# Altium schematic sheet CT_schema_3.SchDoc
size 294 x 169 mm
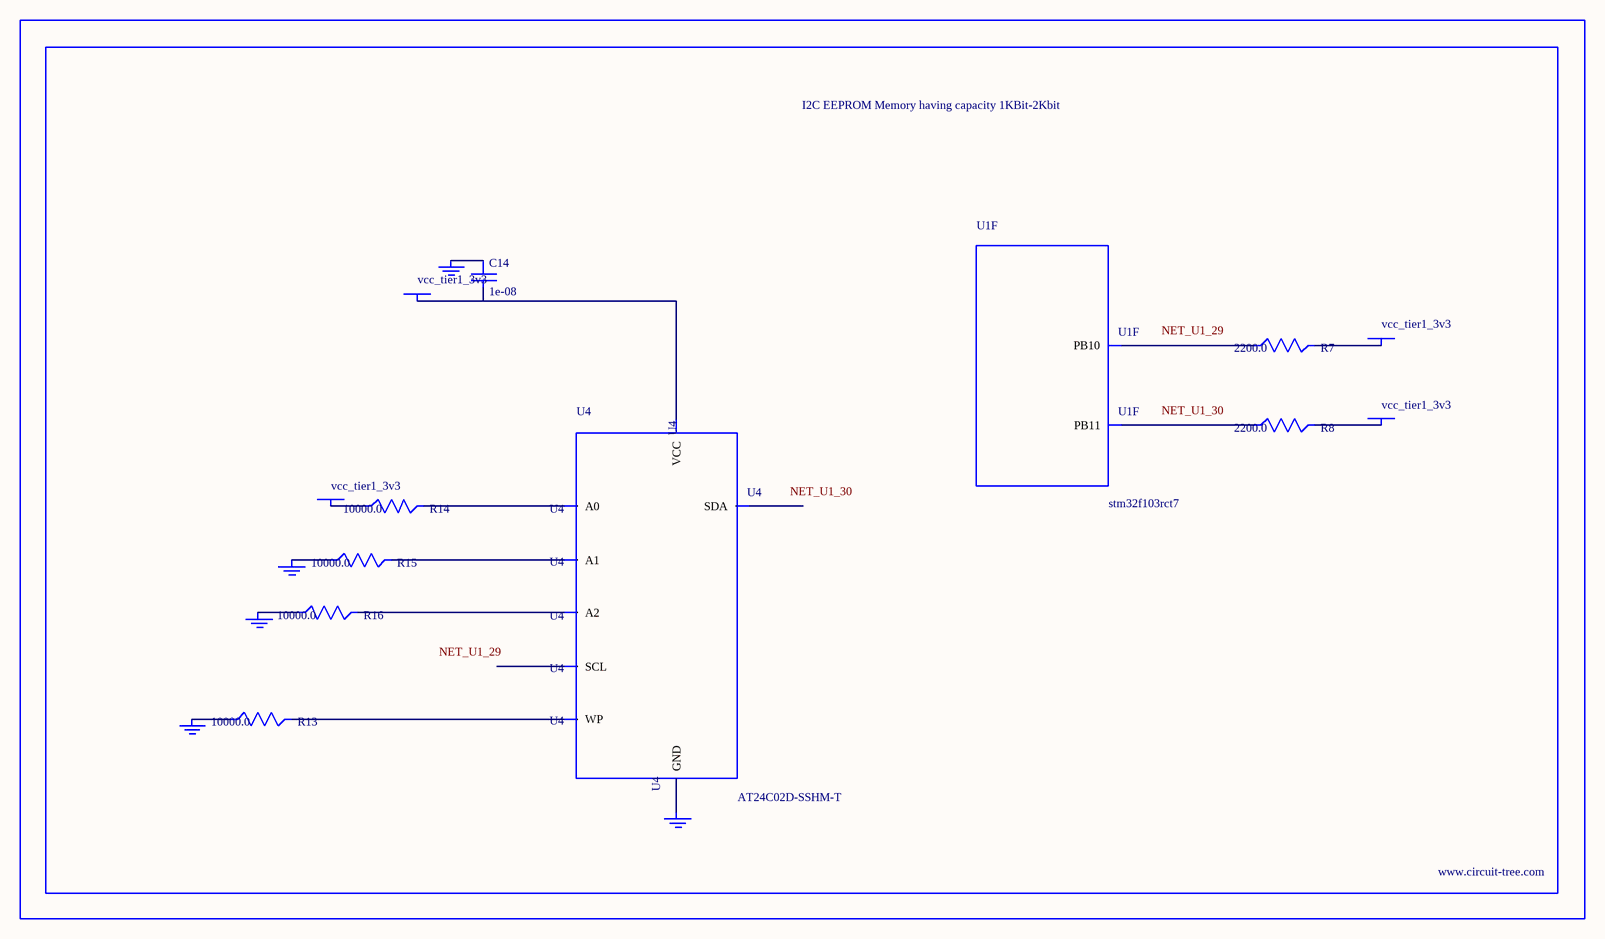
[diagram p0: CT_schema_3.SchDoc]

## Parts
BORDER2  (no value)
C14  1e-08  [C0402]
GND_INSTANCE_2_0  (no value)
GND_INSTANCE_2_1  (no value)
GND_INSTANCE_2_2  (no value)
GND_INSTANCE_2_3  (no value)
GND_INSTANCE_2_4  (no value)
POWER_INSTANCE_2_0  vcc_tier1_3v3
POWER_INSTANCE_2_1  vcc_tier1_3v3
POWER_INSTANCE_2_2  vcc_tier1_3v3
POWER_INSTANCE_2_3  vcc_tier1_3v3
R7  2200.0  [R0603]
R8  2200.0  [R0603]
R13  10000.0  [R0603]
R14  10000.0  [R0603]
R15  10000.0  [R0603]
R16  10000.0  [R0603]
U1  stm32f103rct7  [LQFP64]  (part F of 9)
U4  AT24C02D-SSHM-T  [AT24C02D]

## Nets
NetC14_1: C14.1 GND_INSTANCE_2_3.0(GND)
NetC14_2: C14.2 POWER_INSTANCE_2_1.0(PWR) U4.8(VCC)
NetGND_INSTANCE_2_0_0: GND_INSTANCE_2_0.0(GND) R15.1
NetGND_INSTANCE_2_1_0: GND_INSTANCE_2_1.0(GND) R16.1
NetGND_INSTANCE_2_2_0: GND_INSTANCE_2_2.0(GND) R13.1
NetGND_INSTANCE_2_4_0: GND_INSTANCE_2_4.0(GND) U4.4(GND)
NetPOWER_INSTANCE_2_0_0: POWER_INSTANCE_2_0.0(PWR) R14.1
NetPOWER_INSTANCE_2_2_0: POWER_INSTANCE_2_2.0(PWR) R7.2
NetPOWER_INSTANCE_2_3_0: POWER_INSTANCE_2_3.0(PWR) R8.2
NetR7_1: R7.1 U1.29(PB10)
NetR8_1: R8.1 U1.30(PB11)
NetR13_2: R13.2 U4.7(WP)
NetR14_2: R14.2 U4.1(A0)
NetR15_2: R15.2 U4.2(A1)
NetR16_2: R16.2 U4.3(A2)

Not connected (* = marked no-connect by the designer): U4 5(SDA) 6(SCL)

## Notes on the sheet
- Labels drawn without touching a wire or pin: NET_U1_29, NET_U1_30

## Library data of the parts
BORDER2 = BORDER_PAGE2
C14 = C0402C103K3RAC
GND_INSTANCE_2_0-GND_INSTANCE_2_4 = GND
POWER_INSTANCE_2_0-POWER_INSTANCE_2_3 = PWR
R7 R8 = RC0603JR-072K2L
R13-R16 = RC0603JR-0710KL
